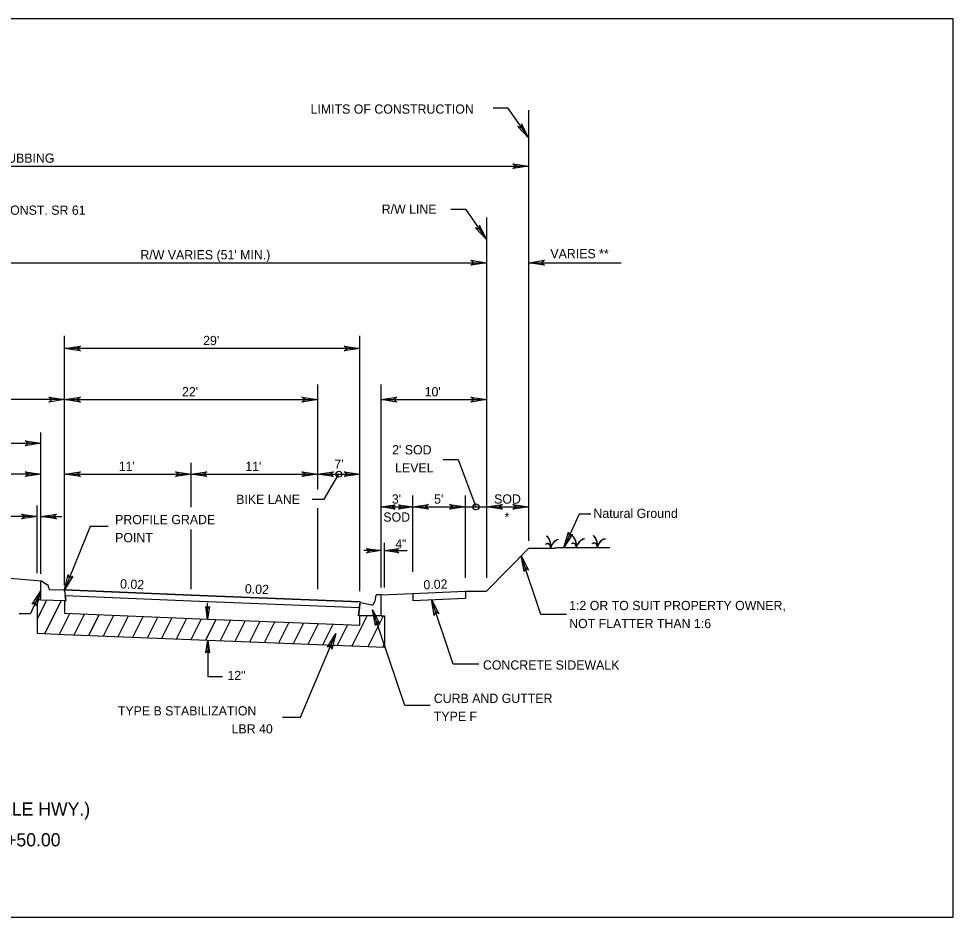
# Model space of a CAD drawing. Extents: x 1477 to 1648, y 601 to 679.
# Drawn here: x 1566.4 to 1647.6, y 600.9 to 679 of the extents above; entities that cross this region are included whole.
import ezdxf

# ---------------------------------------------------------------- set-up
doc = ezdxf.new("R2010")
doc.units = 0
for name, color, linetype in [('CandG_px', 7, 'Continuous'), ('ClipDrawingBound_dp', 7, 'Continuous'), ('ConstLimits', 7, 'Continuous'), ('DimLines_dp', 7, 'Continuous'), ('LeaderLine_dp', 7, 'Continuous'), ('PavtBase_px', 7, 'Continuous'), ('PavtMisc', 7, 'Continuous'), ('PavtStabilization', 7, 'Continuous'), ('RWLine', 7, 'Continuous'), ('Sidewalk_px', 7, 'Continuous'), ('Sod', 7, 'Continuous'), ('TextMisc', 7, 'Continuous'), ('TextTitle', 7, 'Continuous'), ('XSTypical_px', 7, 'Continuous')]:
    doc.layers.add(name, color=color, linetype=linetype)

msp = doc.modelspace()

# ---------------------------------------------------------------- linework, layer by layer
at = {"layer": 'CandG_px'}
for p, q in [((1568.311, 628.495), (1568.311, 630.048)), ((1568.399, 630.121), (1568.902, 629.806)), ((1568.999, 629.542), (1568.999, 629.524)), ((1569.058, 629.401), (1570.309, 629.353)), ((1570.366, 629.287), (1570.497, 628.43)), ((1597.38, 628.736), (1597.321, 628.374)), ((1597.875, 628.945), (1597.526, 628.945)), ((1597.875, 627.109), (1597.875, 628.945)), ((1568.311, 628.495), (1570.497, 628.43)), ((1596, 627.803), (1595.918, 627.109)), ((1596.04, 628.149), (1596, 627.803)), ((1596.101, 628.271), (1597.082, 628.063)), ((1597.875, 627.109), (1595.918, 627.109))]:
    msp.add_line(p, q, dxfattribs=at)
for centre, major_axis, ratio, start_param, end_param in [((1568.373, 630.047), (0, -0.0816), 0.748839, 2.690765, 4.712389), ((1568.861, 629.543), (0, 0.275), 0.499226, 4.712389, 5.977306), ((1569.06, 629.525), (0, -0.122), 0.499226, 4.712389, 6.258499), ((1570.306, 629.271), (0, 0.0816), 0.748839, 4.911887, 6.253817), ((1597.526, 628.639), (0, 0.306), 0.499226, 0, 1.249046), ((1596.101, 628.149), (0, 0.122), 0.499226, 0, 1.570796), ((1597.104, 628.52), (0, -0.459), 0.499226, 6.183517, 7.528486)]:
    msp.add_ellipse(centre, major_axis=major_axis, ratio=ratio, start_param=start_param, end_param=end_param, dxfattribs=at)
at = {"layer": 'ClipDrawingBound_dp'}
msp.add_lwpolyline([(1476.944, 678.987), (1476.944, 600.914), (1647.602, 600.914), (1647.602, 678.987)], close=True, dxfattribs=at)
at = {"layer": 'ConstLimits'}
msp.add_line((1610.709, 633.616), (1610.709, 671.034), dxfattribs=at)
at = {"layer": 'DimLines_dp'}
for p, q in [((1509.875, 666.184), (1610.709, 666.184)), ((1560.292, 657.789), (1607.042, 657.789)), ((1610.709, 657.789), (1618.742, 657.789)), ((1570.375, 629.733), (1570.375, 651.436)), ((1596.042, 629.262), (1596.042, 651.423)), ((1596.042, 650.34), (1570.375, 650.34)), ((1592.375, 638.092), (1592.375, 647.199)), ((1597.875, 629.566), (1597.875, 647.199)), ((1570.377, 645.888), (1550.209, 645.888)), ((1570.375, 645.888), (1592.375, 645.888)), ((1568.311, 630.767), (1568.311, 643.039)), ((1552.271, 642.096), (1568.311, 642.096)), ((1581.375, 636.553), (1581.375, 640.388)), ((1568.313, 639.406), (1560.292, 639.406)), ((1570.378, 639.406), (1581.375, 639.406)), ((1581.375, 639.406), (1592.375, 639.406)), ((1592.375, 639.406), (1596.042, 639.406)), ((1600.625, 630.926), (1600.625, 637.553)), ((1605.209, 630.41), (1605.209, 637.553)), ((1568.006, 630.808), (1568.006, 636.7)), ((1592.375, 629.416), (1592.375, 636.463)), ((1597.875, 636.568), (1600.625, 636.568)), ((1600.625, 636.568), (1605.209, 636.568)), ((1605.209, 636.568), (1607.042, 636.568)), ((1607.042, 636.568), (1610.709, 636.568)), ((1568.006, 635.727), (1565.353, 635.727)), ((1568.311, 635.727), (1570.139, 635.727)), ((1581.375, 629.43), (1581.375, 634.594)), ((1597.854, 632.771), (1596.381, 632.771)), ((1598.181, 629.566), (1598.181, 633.437)), ((1598.182, 632.771), (1600.131, 632.771)), ((1568.311, 629.271), (1567.41, 627.318)), ((1582.802, 626.831), (1582.802, 628.231)), ((1566.432, 627.318), (1567.41, 627.318))]:
    msp.add_line(p, q, dxfattribs=at)
for points in [[(1607.61, 671.241), (1608.876, 671.241), (1610.709, 668.606)], [(1603.943, 662.432), (1605.209, 662.432), (1607.042, 659.797)], [(1603.28, 640.696), (1604.575, 640.696), (1606.125, 636.568)], [(1591.902, 637.256), (1592.921, 637.256), (1594.209, 639.406)], [(1616.114, 635.951), (1615.1, 635.951), (1613.766, 633.034)], [(1574.176, 634.877), (1572.592, 634.877), (1570.375, 629.351)], [(1613.989, 627.221), (1611.771, 627.221), (1610.056, 632.321)], [(1606.363, 622.904), (1604.145, 622.904), (1602.258, 628.517)], [(1602.149, 619.329), (1599.931, 619.329), (1597.14, 627.631)], [(1589.303, 618.313), (1590.875, 618.313), (1593.957, 625.559)], [(1582.812, 624.997), (1582.812, 621.832), (1584.106, 621.839)]]:
    msp.add_lwpolyline(points, dxfattribs=at)
at = {"layer": 'LeaderLine_dp'}
for p, q in [((1610.08, 669.509), (1609.754, 669.617)), ((1609.754, 669.617), (1610.709, 668.606)), ((1610.093, 669.853), (1610.08, 669.509)), ((1610.709, 668.606), (1610.093, 669.853)), ((1609.609, 666.184), (1609.334, 666.391)), ((1609.334, 666.391), (1610.709, 666.184)), ((1610.709, 666.184), (1609.334, 665.978)), ((1609.334, 665.978), (1609.609, 666.184)), ((1606.414, 660.7), (1606.087, 660.808)), ((1606.087, 660.808), (1607.042, 659.797)), ((1606.426, 661.044), (1606.414, 660.7)), ((1607.042, 659.797), (1606.426, 661.044)), ((1605.942, 657.789), (1605.667, 657.995)), ((1605.667, 657.995), (1607.042, 657.789)), ((1610.709, 657.789), (1612.084, 657.995)), ((1612.084, 657.995), (1611.809, 657.789)), ((1607.042, 657.789), (1605.667, 657.583)), ((1605.667, 657.583), (1605.942, 657.789)), ((1612.084, 657.583), (1610.709, 657.789)), ((1611.809, 657.789), (1612.084, 657.583)), ((1570.375, 650.34), (1571.75, 650.546)), ((1571.75, 650.546), (1571.475, 650.34)), ((1594.942, 650.34), (1594.667, 650.546)), ((1594.667, 650.546), (1596.042, 650.34)), ((1571.75, 650.134), (1570.375, 650.34)), ((1571.475, 650.34), (1571.75, 650.134)), ((1596.042, 650.34), (1594.667, 650.134)), ((1594.667, 650.134), (1594.942, 650.34)), ((1569.277, 645.888), (1569.002, 646.095)), ((1569.002, 646.095), (1570.377, 645.888)), ((1570.377, 645.888), (1569.002, 645.682)), ((1569.002, 645.682), (1569.277, 645.888)), ((1570.375, 645.888), (1571.75, 646.095)), ((1571.75, 645.682), (1570.375, 645.888)), ((1571.75, 646.095), (1571.475, 645.888)), ((1571.475, 645.888), (1571.75, 645.682)), ((1591.275, 645.888), (1591, 646.095)), ((1591, 646.095), (1592.375, 645.888)), ((1592.375, 645.888), (1591, 645.682)), ((1591, 645.682), (1591.275, 645.888)), ((1597.875, 645.888), (1599.25, 646.095)), ((1599.25, 645.682), (1597.875, 645.888)), ((1599.25, 646.095), (1598.975, 645.888)), ((1598.975, 645.888), (1599.25, 645.682)), ((1605.942, 645.888), (1605.667, 646.095)), ((1605.667, 646.095), (1607.042, 645.888)), ((1607.042, 645.888), (1605.667, 645.682)), ((1605.667, 645.682), (1605.942, 645.888)), ((1567.211, 642.096), (1566.936, 642.302)), ((1566.936, 642.302), (1568.311, 642.096)), ((1568.311, 642.096), (1566.936, 641.89)), ((1566.936, 641.89), (1567.211, 642.096)), ((1567.213, 639.406), (1566.938, 639.612)), ((1566.938, 639.612), (1568.313, 639.406)), ((1568.313, 639.406), (1566.938, 639.2)), ((1566.938, 639.2), (1567.213, 639.406)), ((1570.378, 639.406), (1571.753, 639.612)), ((1571.753, 639.2), (1570.378, 639.406)), ((1571.753, 639.612), (1571.478, 639.406)), ((1571.478, 639.406), (1571.753, 639.2)), ((1580.275, 639.406), (1580, 639.612)), ((1580, 639.612), (1581.375, 639.406)), ((1581.375, 639.406), (1580, 639.2)), ((1580, 639.2), (1580.275, 639.406)), ((1581.375, 639.406), (1582.75, 639.612)), ((1582.75, 639.2), (1581.375, 639.406)), ((1582.75, 639.612), (1582.475, 639.406)), ((1582.475, 639.406), (1582.75, 639.2)), ((1591.275, 639.406), (1591, 639.612)), ((1591, 639.612), (1592.375, 639.406)), ((1592.375, 639.406), (1591, 639.2)), ((1591, 639.2), (1591.275, 639.406)), ((1592.375, 639.406), (1593.75, 639.612)), ((1593.75, 639.2), (1592.375, 639.406)), ((1593.75, 639.612), (1593.475, 639.406)), ((1593.475, 639.406), (1593.75, 639.2)), ((1594.942, 639.406), (1594.667, 639.612)), ((1594.667, 639.612), (1596.042, 639.406)), ((1596.042, 639.406), (1594.667, 639.2)), ((1594.667, 639.2), (1594.942, 639.406)), ((1597.875, 636.568), (1599.113, 636.753)), ((1599.113, 636.753), (1598.865, 636.568)), ((1599.635, 636.568), (1599.388, 636.753)), ((1599.388, 636.753), (1600.625, 636.568)), ((1600.625, 636.568), (1602, 636.774)), ((1602, 636.774), (1601.725, 636.568)), ((1604.109, 636.568), (1603.834, 636.774)), ((1603.834, 636.774), (1605.209, 636.568)), ((1607.042, 636.568), (1608.417, 636.774)), ((1608.417, 636.774), (1608.142, 636.568)), ((1609.609, 636.568), (1609.334, 636.774)), ((1609.334, 636.774), (1610.709, 636.568)), ((1566.906, 635.727), (1566.631, 635.933)), ((1566.631, 635.933), (1568.006, 635.727)), ((1568.311, 635.727), (1569.686, 635.933)), ((1569.686, 635.933), (1569.411, 635.727)), ((1599.113, 636.382), (1597.875, 636.568)), ((1598.865, 636.568), (1599.113, 636.382)), ((1600.625, 636.568), (1599.388, 636.382)), ((1599.388, 636.382), (1599.635, 636.568)), ((1602, 636.362), (1600.625, 636.568)), ((1601.725, 636.568), (1602, 636.362)), ((1605.209, 636.568), (1603.834, 636.362)), ((1603.834, 636.362), (1604.109, 636.568)), ((1608.417, 636.362), (1607.042, 636.568)), ((1608.142, 636.568), (1608.417, 636.362)), ((1610.709, 636.568), (1609.334, 636.362)), ((1609.334, 636.362), (1609.609, 636.568)), ((1568.006, 635.727), (1566.631, 635.521)), ((1566.631, 635.521), (1566.906, 635.727)), ((1569.686, 635.521), (1568.311, 635.727)), ((1569.411, 635.727), (1569.686, 635.521)), ((1613.766, 633.034), (1614.15, 634.37)), ((1614.15, 634.37), (1614.223, 634.034)), ((1614.525, 634.199), (1613.766, 633.034)), ((1614.223, 634.034), (1614.525, 634.199)), ((1596.864, 632.771), (1596.617, 632.957)), ((1596.617, 632.957), (1597.854, 632.771)), ((1597.854, 632.771), (1596.617, 632.585)), ((1596.617, 632.585), (1596.864, 632.771)), ((1598.182, 632.771), (1599.419, 632.957)), ((1599.419, 632.585), (1598.182, 632.771)), ((1599.419, 632.957), (1599.172, 632.771)), ((1599.172, 632.771), (1599.419, 632.585)), ((1610.056, 632.321), (1610.69, 631.083)), ((1610.299, 630.952), (1610.056, 632.321)), ((1610.407, 631.278), (1610.299, 630.952)), ((1610.69, 631.083), (1610.407, 631.278)), ((1570.375, 629.351), (1570.696, 630.704)), ((1571.079, 630.55), (1570.375, 629.351)), ((1570.696, 630.704), (1570.785, 630.372)), ((1570.785, 630.372), (1571.079, 630.55)), ((1567.548, 628.109), (1568.311, 629.271)), ((1568.311, 629.271), (1567.922, 627.936)), ((1567.85, 628.272), (1567.548, 628.109)), ((1567.922, 627.936), (1567.85, 628.272)), ((1582.802, 626.831), (1582.637, 627.931)), ((1582.637, 627.931), (1582.802, 627.711)), ((1582.802, 627.711), (1582.967, 627.931)), ((1582.967, 627.931), (1582.802, 626.831)), ((1602.258, 628.517), (1602.892, 627.279)), ((1602.501, 627.148), (1602.258, 628.517)), ((1597.14, 627.631), (1597.773, 626.394)), ((1597.382, 626.262), (1597.14, 627.631)), ((1602.609, 627.474), (1602.501, 627.148)), ((1602.892, 627.279), (1602.609, 627.474)), ((1597.49, 626.589), (1597.382, 626.262)), ((1597.773, 626.394), (1597.49, 626.589)), ((1593.229, 624.374), (1593.957, 625.559)), ((1593.957, 625.559), (1593.609, 624.213)), ((1582.647, 623.897), (1582.812, 624.997)), ((1582.812, 624.997), (1582.977, 623.897)), ((1593.527, 624.546), (1593.229, 624.374)), ((1593.609, 624.213), (1593.527, 624.546)), ((1582.812, 624.117), (1582.647, 623.897)), ((1582.977, 623.897), (1582.812, 624.117))]:
    msp.add_line(p, q, dxfattribs=at)
at = {"layer": 'PavtBase_px'}
for p, q in [((1570.497, 628.43), (1570.431, 628.859)), ((1570.375, 628.433), (1570.375, 627.325)), ((1570.375, 628.433), (1570.497, 628.43)), ((1595.918, 627.109), (1596.004, 627.834)), ((1570.38, 627.328), (1582.802, 626.831)), ((1596.041, 627.109), (1595.918, 627.109)), ((1596.041, 626.302), (1596.041, 627.109)), ((1582.802, 626.831), (1592.375, 626.449)), ((1592.375, 626.449), (1596.041, 626.302))]:
    msp.add_line(p, q, dxfattribs=at)
at = {"layer": 'PavtMisc'}
for p, q in [((1581.374, 628.91), (1570.309, 629.353)), ((1570.365, 629.287), (1570.43, 628.859)), ((1570.431, 628.859), (1581.375, 628.42)), ((1592.375, 628.47), (1581.374, 628.91)), ((1581.375, 628.42), (1592.375, 627.979)), ((1596.041, 628.321), (1592.375, 628.47)), ((1592.375, 627.98), (1596, 627.834)), ((1596.005, 627.833), (1596.041, 628.149))]:
    msp.add_line(p, q, dxfattribs=at)
for centre, major_axis, ratio, start_param, end_param in [((1570.306, 629.271), (0, 0.0816), 0.748839, 4.911887, 6.253817), ((1596.101, 628.149), (0, 0.122), 0.499226, 0, 1.570796), ((1596.034, 628.213), (0, 0.109), 0.732639, 5.27008, 6.194042)]:
    msp.add_ellipse(centre, major_axis=major_axis, ratio=ratio, start_param=start_param, end_param=end_param, dxfattribs=at)
at = {"layer": 'PavtStabilization'}
for p, q in [((1568.311, 628.495), (1568.006, 628.495)), ((1568.006, 628.495), (1568.006, 625.594)), ((1568.006, 626.826), (1568.83, 628.479)), ((1568.671, 625.563), (1570.108, 628.442)), ((1569.942, 625.511), (1570.84, 627.31)), ((1571.212, 625.46), (1572.111, 627.259)), ((1572.484, 625.409), (1573.382, 627.209)), ((1573.755, 625.36), (1574.653, 627.157)), ((1575.026, 625.307), (1575.924, 627.106)), ((1576.296, 625.257), (1577.195, 627.056)), ((1577.568, 625.208), (1578.466, 627.004)), ((1595.362, 624.493), (1596.667, 627.109)), ((1596.761, 624.438), (1598.095, 627.109)), ((1597.875, 627.109), (1598.18, 627.109)), ((1598.18, 627.109), (1598.18, 624.382)), ((1578.839, 625.156), (1579.737, 626.954)), ((1580.11, 625.104), (1581.008, 626.903)), ((1581.381, 625.054), (1582.278, 626.853)), ((1582.652, 625.003), (1583.55, 626.803)), ((1583.922, 624.952), (1584.82, 626.75)), ((1585.193, 624.9), (1586.092, 626.701)), ((1586.465, 624.85), (1587.363, 626.649)), ((1587.735, 624.799), (1588.634, 626.598)), ((1589.007, 624.749), (1589.904, 626.547)), ((1590.277, 624.697), (1591.176, 626.496)), ((1591.549, 624.646), (1592.447, 626.445)), ((1592.819, 624.596), (1593.717, 626.395)), ((1594.091, 624.546), (1594.988, 626.343)), ((1568.006, 625.588), (1570.375, 625.494)), ((1570.375, 625.494), (1582.802, 624.997)), ((1582.802, 624.997), (1592.375, 624.614)), ((1592.375, 624.614), (1596.042, 624.467)), ((1598.031, 624.387), (1598.18, 624.684)), ((1596.042, 624.467), (1598.18, 624.382))]:
    msp.add_line(p, q, dxfattribs=at)
at = {"layer": 'RWLine'}
msp.add_line((1607.042, 661.717), (1607.042, 630.41), dxfattribs=at)
at = {"layer": 'Sidewalk_px'}
for p, q in [((1600.625, 629.055), (1605.2, 629.238)), ((1600.625, 629.055), (1600.625, 628.443)), ((1600.625, 628.443), (1605.2, 628.627)), ((1605.2, 629.238), (1605.2, 628.627))]:
    msp.add_line(p, q, dxfattribs=at)
at = {"layer": 'Sod'}
for p, q in [((1607.041, 629.238), (1610.711, 632.991)), ((1568.358, 630.125), (1560.292, 630.771)), ((1597.875, 628.945), (1600.625, 629.055)), ((1605.2, 629.238), (1607.041, 629.238))]:
    msp.add_line(p, q, dxfattribs=at)
msp.add_lwpolyline([(1610.711, 632.991), (1610.908, 632.991), (1610.972, 632.991), (1611.036, 632.991), (1611.099, 632.991), (1611.163, 632.991), (1611.242, 632.991), (1611.306, 632.991), (1611.369, 632.991), (1611.433, 632.991), (1611.496, 632.991), (1611.559, 632.991), (1611.623, 632.991), (1611.702, 632.991), (1611.766, 632.991), (1611.83, 632.991), (1611.893, 632.991), (1611.957, 632.991), (1612.021, 632.991), (1612.085, 632.991), (1612.164, 632.991), (1612.228, 632.991), (1612.291, 632.991), (1612.354, 632.991), (1612.417, 632.991), (1612.482, 632.991), (1612.561, 632.991), (1612.64, 632.991), (1612.704, 632.991), (1612.783, 632.991), (1612.863, 632.991), (1612.943, 632.991), (1613.006, 633.013), (1613.069, 633.013), (1613.133, 633.013), (1613.213, 633.034), (1613.276, 633.034), (1613.34, 633.034), (1613.419, 633.034), (1613.483, 633.034), (1613.546, 633.034), (1617.756, 633.034)], dxfattribs=at)
for centre, major_axis, ratio in [((1612.292, 634.02), (0.00348, 0.00738), 0.389816), ((1613.298, 633.74), (0.0015, -0.0123), 0.218972), ((1614.514, 634.054), (0.00348, 0.00738), 0.389816), ((1615.52, 633.775), (0.0015, -0.0123), 0.218972), ((1616.336, 634.071), (0.00348, 0.00738), 0.389816), ((1617.341, 633.792), (0.0015, -0.0123), 0.218972), ((1612.204, 633.324), (-0.00319, 0.0083), 0.334101), ((1614.426, 633.359), (-0.00319, 0.0083), 0.334101), ((1616.247, 633.376), (-0.00319, 0.0083), 0.334101)]:
    msp.add_ellipse(centre, major_axis=major_axis, ratio=ratio, dxfattribs=at)
for centre, major_axis, start_param, end_param in [((1611.9, 633.205), (0, -0.96), 1.43816, 2.57018), ((1611.9, 633.205), (0, -0.978), 1.375837, 2.57018), ((1613.415, 632.603), (0, 1.136), 0.136484, 1.211739), ((1613.415, 632.603), (0, 1.16), 0.136484, 1.135245), ((1614.122, 633.24), (0, -0.96), 1.43816, 2.57018), ((1614.122, 633.24), (0, -0.978), 1.375837, 2.57018), ((1615.637, 632.638), (0, 1.136), 0.136484, 1.211739), ((1615.637, 632.638), (0, 1.16), 0.136484, 1.135245), ((1615.943, 633.256), (0, -0.96), 1.43816, 2.57018), ((1615.943, 633.256), (0, -0.978), 1.375837, 2.57018), ((1617.458, 632.654), (0, 1.136), 0.136484, 1.211739), ((1617.458, 632.654), (0, 1.16), 0.136484, 1.135245), ((1612.345, 633.001), (0, 0.383), 5.050826, 6.812464), ((1612.345, 633.001), (0, 0.365), 4.696782, 6.812464), ((1614.567, 633.036), (0, 0.383), 5.050826, 6.812464), ((1614.567, 633.036), (0, 0.365), 4.696782, 6.812464), ((1616.389, 633.053), (0, 0.383), 5.050826, 6.812464), ((1616.389, 633.053), (0, 0.365), 4.696782, 6.812464)]:
    msp.add_ellipse(centre, major_axis=major_axis, ratio=0.748839, start_param=start_param, end_param=end_param, dxfattribs=at)
at = {"layer": 'TextMisc'}
msp.add_line((1597.875, 645.888), (1607.042, 645.888), dxfattribs=at)
for centre in [(1594.209, 639.406), (1606.125, 636.568)]:
    msp.add_circle(centre, 0.255, dxfattribs=at)
at = {"layer": 'XSTypical_px'}
for p, q in [((1570.309, 629.353), (1581.374, 628.91)), ((1570.431, 628.859), (1581.375, 628.42)), ((1581.374, 628.91), (1592.375, 628.47)), ((1581.375, 628.42), (1592.375, 627.979)), ((1592.375, 628.47), (1596.041, 628.321)), ((1592.375, 627.98), (1596.004, 627.834))]:
    msp.add_line(p, q, dxfattribs=at)
msp.add_ellipse((1596.034, 628.213), major_axis=(0, 0.109), ratio=0.732639, start_param=5.27008, end_param=6.194387, dxfattribs=at)

# ---------------------------------------------------------------- texts
at = {"layer": 'TextMisc'}
for s, height, p in [('LIMITS OF CONSTRUCTION', 0.80208, (1591.751, 670.734)), ('STANDARD CLEARING AND GRUBBING', 0.80208, (1549.231, 666.471)), ('℄ CONST. SR 61', 0.80208, (1564.136, 661.951)), ('R/W LINE', 0.8021, (1597.93, 662.038)), ("R/W VARIES (51' MIN.)", 0.80208, (1576.962, 658.076)), ('VARIES **', 0.8021, (1612.589, 658.174)), ("29'", 0.8021, (1582.414, 650.627)), ("22'", 0.8021, (1580.581, 646.175)), ("10'", 0.8021, (1601.664, 646.175)), ("2' SOD ", 0.8021, (1598.841, 641.132)), ("11'", 0.8021, (1575.082, 639.692)), ("11'", 0.8021, (1586.081, 639.692)), ("7'", 0.8021, (1593.815, 639.886)), ('LEVEL ', 0.8021, (1599.097, 639.566)), ('BIKE LANE', 0.8021, (1585.286, 636.825)), ("3'", 0.8021, (1598.816, 636.854)), ("5'", 0.8021, (1602.483, 636.854)), ('SOD', 0.8021, (1607.699, 636.854)), ('SOD', 0.8021, (1598.074, 635.289)), ('*', 0.802, (1608.609, 635.289)), ('Natural Ground', 0.80208, (1616.329, 635.612)), ('PROFILE GRADE', 0.80208, (1574.767, 635.068)), ('POINT', 0.8021, (1574.767, 633.503)), ('4"', 0.7636, (1599.13, 632.984)), ('1:2 OR TO SUIT PROPERTY OWNER,', 0.80208, (1614.221, 627.602)), ('NOT FLATTER THAN 1:6', 0.80208, (1614.221, 626.037)), ('CONCRETE SIDEWALK', 0.80208, (1606.729, 622.435)), ('12"', 0.8021, (1584.524, 621.522)), ('CURB AND GUTTER', 0.80208, (1602.46, 619.536)), ('TYPE B STABILIZATION', 0.80208, (1575.004, 618.451)), ('TYPE F', 0.8021, (1602.46, 617.97)), ('LBR 40', 0.8021, (1584.888, 616.886))]:
    msp.add_text(s, height=height, dxfattribs=at).set_placement(p)
for rotation, p in [(357.70863, (1575.187, 629.495)), (2.2952, (1601.574, 629.397)), (357.70958, (1586.031, 629.066))]:
    msp.add_text('0.02', height=0.8021, rotation=rotation, dxfattribs=at).set_placement(p)
at = {"layer": 'TextTitle'}
for s, p in [('SR 61 (US 319) (CRAWFORDVILLE HWY.)', (1542.712, 609.75)), ('STA. 700+00.00 TO STA. 715+50.00', (1544.81, 607.077))]:
    msp.add_text(s, height=1.14583, dxfattribs=at).set_placement(p)

doc.saveas('drawing.dxf')
